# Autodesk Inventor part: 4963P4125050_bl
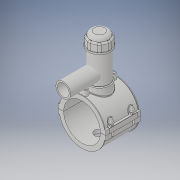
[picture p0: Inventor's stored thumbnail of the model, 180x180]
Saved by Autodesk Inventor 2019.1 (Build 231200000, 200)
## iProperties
Created: 2017-07
Part Number: 4963P4125050_bl
Material: Generic
Document SubType Name: Modeling
Designer: KIM
Density: 1 g/cm^3
Appearance: Default
Author: KIM
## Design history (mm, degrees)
derived "4963P4.ipt"
feature "Solid1::4963P4.ipt" dims "ScaleForDerivedMember" = 10
feature "Solid2::4963P4.ipt" dims "ScaleForDerivedMember" = 10
feature "Solid3::4963P4.ipt" dims "ScaleForDerivedMember" = 10
tag "TaggingFeature1"
body "Solid1"
body "Solid2"
body "Solid3"
other parameters: "d0" = 125 [user parameter], "d2" = 162 [user parameter], "d3" = 31.25 [user parameter], "d4" = 118 [user parameter], "d5" = 0 [user parameter], "d6" = 0.1 [user parameter], "d8" = 0 [user parameter], "d19" = 6 [user parameter], "d20" = 6 [user parameter], "d21" = 70.8 [user parameter], "d23" = 0 [user parameter], "d24" = 35.4 [user parameter], "d26" = 0 [user parameter], "d27" = 3 [user parameter], "d28" = 3 [user parameter], "d29" = 3 [user parameter], "d30" = 41.66667 [user parameter], "d31" = 6 [user parameter], "d32" = 0 [user parameter], "d33" = 0 [user parameter], "d34" = 0.6 [user parameter], "d40" = 79.3 [user parameter], "d41" = 75 [user parameter], "d43" = 0 [user parameter], "d45" = 0 [user parameter], "d47" = 147.05 [user parameter], "d70" = 15 [user parameter], "d72" = 0 [user parameter], "d73" = 6 [user parameter], "d75" = 5 [user parameter], "d76" = 0 [user parameter], "d77" = 6.25 [user parameter], "d78" = 92.5 [user parameter], "d79" = 15 [user parameter], "d80" = 47.2 [user parameter], "d82" = 5 deg [user parameter], "d84" = 4 [user parameter], "d85" = 14 [user parameter], "d86" = 0 [user parameter], "d87" = 3 [user parameter], "d88" = 0 [user parameter], "d89" = 1 [user parameter], "d90" = 1 [user parameter], "d91" = 94.4 [user parameter], "d92" = 0 [user parameter], "d93" = 0.5 [user parameter], "d94" = 65.78947 [user parameter], "d96" = 155.55 [user parameter], "d97" = 2.36 [user parameter], "d98" = 0 [user parameter], "d102" = 1.25 [user parameter], "d120" = 140 deg [user parameter], "d121" = 24.228 [user parameter], "d122" = 20 deg [user parameter], "d123" = 305 [user parameter], "d124" = 91.5 [user parameter], "d126" = 0 [user parameter], "d143" = 128.75 [user parameter], "d145" = 21.15385 [user parameter], "d149" = 1.875 [user parameter], "d150" = 23.26923 [user parameter], "d153" = 118 [user parameter], "d154" = 0 [user parameter], "d156" = 76.25 [user parameter], "d157" = 160 deg [user parameter], "d159" = 5.5 [user parameter], "d161" = 1.875 [user parameter], "d162" = 70.8 [user parameter], "d163" = 0 [user parameter], "d164" = 62.5 [user parameter], "d167" = 12.5 [user parameter], "d168" = 74.39024 [user parameter], "d170" = 3.75 [user parameter], "d172" = 0 [user parameter], "d173" = 1 [user parameter], "d175" = 62.5 [user parameter], "d176" = 20 deg [user parameter], "d177" = 8.75 [user parameter], "d178" = 27.5 [user parameter], "d180" = 0 [user parameter], "d183" = 11 [user parameter], "d184" = 7 [user parameter], "d185" = 38.35 [user parameter], "d186" = 38.35 [user parameter], "d187" = 76.25 [user parameter], "d188" = 8.25 [user parameter], "d189" = 8.75 [user parameter], "d190" = 0 [user parameter], "d191" = 114.375 [user parameter], "d193" = 8 [user parameter], "d194" = 4.13 [user parameter], "d195" = 90 deg [user parameter], "d197" = 0 [user parameter], "d199" = 0 [user parameter], "d200" = 13.75 [user parameter], "d202" = 0 [user parameter], "d203" = 177 [user parameter], "d204" = 71.25 [user parameter], "d205" = 52.5 [user parameter], "d206" = 63.75 [user parameter], "d207" = 132.75 [user parameter], "d208" = 138.06 [user parameter], "d209" = 164.61 [user parameter], "d210" = 64.5 [user parameter], "d211" = 75 [user parameter], "d213" = 35.1 [user parameter], "d216" = 0 [user parameter], "d217" = 12.5 [user parameter], "d218" = 12.5 [user parameter], "d219" = 2.5 [user parameter], "d222" = 125 [user parameter], "d224" = 0 [user parameter], "d225" = 64 [user parameter], "d228" = 123 [user parameter], "d230" = 5 [user parameter], "d_" = 125 [user parameter], "B_" = 162 [user parameter], "L_" = 118 [user parameter], "d_t" = 6 [user parameter], "H_2" = 177 [user parameter]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
